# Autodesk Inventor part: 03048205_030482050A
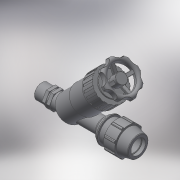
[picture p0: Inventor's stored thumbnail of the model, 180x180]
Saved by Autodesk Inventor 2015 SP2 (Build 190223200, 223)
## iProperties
Created: 2017-02
Part Number: 03048205_030482050A
Material: Generic
Description: PLASSON ANGLE SEAT VALVE 20-1/2"
Document SubType Name: Modeling
Designer: KIM
Mass: 270.157 g
Surface Area: 530.242 cm^2
Volume: 270.157 cm^3
Density: 1 g/cm^3
Appearance: Default
Author: KIM
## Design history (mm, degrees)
derived "03048-03948.ipt"
feature "Solid1::03048-03948.ipt"
tag "TaggingFeature1"
body "Solid1"
other parameters: "E_" = 48, "A_" = 113, "l_" = 57, "H_" = 174, "d224" = 113, "G_" = 20.955, "l_2" = 16, "d202" = 54.918, "d214" = 61.02, "d218" = 61.02, "d225" = 61.02, "d226" = 42.714, "d4" = 7.25, "d5" = 19.14, "d7" = 48, "d11" = 2.48571, "d13" = 120 deg, "d14" = 28, "d15" = 12 deg, "d16" = 41.76, "d18" = 1, "d19" = 35 deg, "d20" = 17.5 deg, "d21" = 44.64, "d23" = 0, "d25" = 360 deg, "d27" = 0.96, "d33" = 0.4, "d42" = 22.62, "d43" = 1.44, "d46" = 0.6, "d63" = 57, "d67" = 36, "d96" = 8.7, "d128" = 174, "d159" = 2, "d165" = 101.7, "d167" = 61.02, "d168" = 18.306, "d169" = 18.306, "d170" = 90 deg, "d171" = 70 deg, "d172" = 14.6448, "d173" = 42.714, "d174" = 42.714, "d175" = 54.918, "d176" = 135 deg, "d177" = 48.816, "d178" = 45.765, "d179" = 25.425, "d180" = 101.7, "d182" = 14.6448, "d183" = 40.2732, "d190" = 45 deg, "d191" = 34.8, "d192" = 2.26, "d193" = 4.52, "d194" = 2.26, "d195" = 53.27046, "d198" = 0, "d199" = 22.8825, "d200" = 113, "d204" = 360 deg, "d209" = 0, "d213" = 3.051, "d216" = 360 deg, "d220" = 51.867, "d221" = 3.39, "d222" = 3.39, "d223" = 6.78, "d227" = 3.39, "d229" = 0, "d230" = 0.565, "d232" = 360 deg, "d234" = 0.565, "d235" = 0.565, "d237" = 360 deg, "d239" = 0.904, "d241" = 0.565, "d249" = 20.955, "d250" = 45 deg, "d251" = 16, "d252" = 174, "d253" = 16, "d254" = 5.33333, "d255" = 2.66667, "d256" = 22, "d258" = 0, "d260" = 0, "d261" = 0.4191, "d265" = 0, "d266" = 113
